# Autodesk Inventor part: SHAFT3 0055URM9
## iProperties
Created: 2004-04
Document SubType Name: Modeling
Manufacturer: Standard
Standards Organization: Custom
Description: Shaft
Density: 1 g/cm^3
+MSCProtocol1+ProtocolID: P00050314163846609
+MSCProtocol2+Protocol: P00050314163846609<@PID>[Version]<@EL>Version=2.0<@EL>[Mechsoft]<@EL>Dynamic=1<@EL>[Synchronize]<@EL>ChangedVars=<@EL>[Debug]<@EL>ChangedVars=<@EL>[Calc]<@EL>Ca
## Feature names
1. Revolution1
2. Circular Pattern1
3. Fillet1
